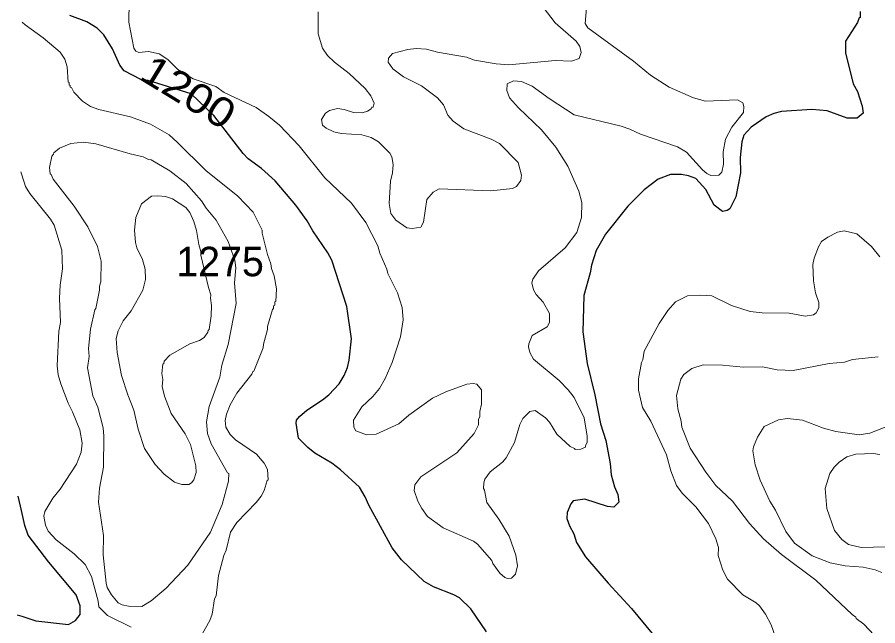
# Model space of a CAD drawing. Extents: x 598.3 to 623.2, y 6902.2 to 6930.1.
# Drawn here: x 598.43 to 600.767, y 6915.078 to 6916.731 of the extents above; entities that cross this region are included whole.
import ezdxf
from ezdxf.enums import TextEntityAlignment as Align

# ---------------------------------------------------------------- set-up
doc = ezdxf.new("R2010")
doc.units = 0
doc.header["$LTSCALE"] = 0.032
doc.layers.add('1', color=7, linetype='Continuous', lineweight=25)
doc.layers.add('2', color=7, linetype='Continuous', lineweight=13)
doc.layers.add('21', color=7, linetype='Continuous')
doc.layers.add('61', color=7, linetype='Continuous')

msp = doc.modelspace()

# ---------------------------------------------------------------- linework, layer by layer
at = {"layer": '1'}
for points in [[(600.719, 6916.7473), (600.719, 6916.7309), (600.7158, 6916.7296), (600.7118, 6916.717), (600.6795, 6916.6668), (600.6793, 6916.6345), (600.6999, 6916.5509), (600.712, 6916.5299), (600.7239, 6916.4898), (600.7269, 6916.4708), (600.7106, 6916.457), (600.6834, 6916.457), (600.6297, 6916.4772), (600.5876, 6916.4812), (600.5053, 6916.4755), (600.4842, 6916.4698), (600.4632, 6916.4609), (600.4225, 6916.4332), (600.4031, 6916.4108), (600.3976, 6916.3926), (600.3927, 6916.3508), (600.3936, 6916.3088), (600.3812, 6916.2431), (600.3648, 6916.2107)], [(599.3178, 6915.7583), (599.3268, 6915.7796), (599.3316, 6915.8002), (599.3379, 6915.8577), (599.3253, 6915.9454), (599.2845, 6916.0711), (599.2734, 6916.0916), (599.2328, 6916.1509), (599.217, 6916.1783), (599.1868, 6916.2211), (599.1306, 6916.2871), (599.093, 6916.3207), (599.0569, 6916.3466), (599.0432, 6916.3611), (598.9638, 6916.4646), (598.9024, 6916.5237), (598.7856, 6916.5597), (598.7659, 6916.5624), (598.7206, 6916.5857), (598.7081, 6916.6013), (598.6887, 6916.6458), (598.6647, 6916.6833), (598.6467, 6916.7013), (598.6191, 6916.7187), (598.5726, 6916.7357)], [(600.3648, 6916.2107), (600.358, 6916.206), (600.3451, 6916.2037), (600.3228, 6916.221), (600.2995, 6916.2637), (600.2729, 6916.2934), (600.2524, 6916.3007), (600.2336, 6916.3039), (600.2039, 6916.3046), (600.17, 6916.2916), (600.1319, 6916.2624), (600.0879, 6916.2184), (600.027, 6916.142), (600.0017, 6916.0974), (599.9889, 6916.0581), (599.9857, 6916.0371), (599.9687, 6915.9755), (599.966, 6915.8771), (599.9775, 6915.7907), (599.9987, 6915.7058), (600.0141, 6915.6264), (600.0285, 6915.5818), (600.0398, 6915.519), (600.0427, 6915.4885), (600.0519, 6915.4559), (600.0609, 6915.4345), (600.0632, 6915.4139), (600.0496, 6915.4006), (600.0329, 6915.4021), (599.971, 6915.4223), (599.9394, 6915.4173), (599.9329, 6915.4095), (599.923, 6915.386), (599.9225, 6915.3697), (599.9292, 6915.3501), (599.941, 6915.328), (599.9488, 6915.3041), (599.9733, 6915.2658), (600.0344, 6915.194), (600.0979, 6915.1255), (600.1538, 6915.0569)], [(599.7041, 6915.0619), (599.6612, 6915.124), (599.6308, 6915.1538), (599.6159, 6915.1624), (599.5601, 6915.1837), (599.5351, 6915.1981), (599.4732, 6915.2572), (599.4484, 6915.2898), (599.3846, 6915.4061), (599.3751, 6915.4283), (599.3592, 6915.4545), (599.3075, 6915.5023), (599.2839, 6915.52), (599.2383, 6915.5473), (599.2188, 6915.5627), (599.194, 6915.5878), (599.1875, 6915.6285), (599.1881, 6915.637), (599.196, 6915.6469), (599.2166, 6915.6644), (599.2591, 6915.6918), (599.2759, 6915.706), (599.3038, 6915.7354), (599.3178, 6915.7583)], [(598.4298, 6915.1084), (598.4423, 6915.1042), (598.4803, 6915.0916), (598.5687, 6915.0817), (598.5881, 6915.0927), (598.6011, 6915.1089), (598.6012, 6915.1326), (598.5901, 6915.1623), (598.5156, 6915.2515), (598.4596, 6915.3243), (598.4506, 6915.351), (598.4412, 6915.3917), (598.4324, 6915.4299)]]:
    msp.add_lwpolyline(points, dxfattribs=at)
at = {"layer": '2'}
for points in [[(598.7342, 6916.7732), (598.7326, 6916.7182), (598.7467, 6916.6478), (598.7518, 6916.6394), (598.7603, 6916.6357), (598.7862, 6916.6382), (598.8154, 6916.6316), (598.8388, 6916.6162), (598.8659, 6916.5894), (598.9076, 6916.5642), (598.9692, 6916.5434), (598.9919, 6916.5272), (599.0788, 6916.4862), (599.1127, 6916.4622), (599.1418, 6916.4379), (599.1959, 6916.3821), (599.2655, 6916.2955), (599.3376, 6916.2267), (599.3765, 6916.1734), (599.4089, 6916.1102), (599.4141, 6916.0902), (599.4334, 6916.0468), (599.4361, 6916.0349), (599.4625, 6915.9823), (599.4756, 6915.9429), (599.478, 6915.909), (599.4707, 6915.8635), (599.4479, 6915.7933), (599.4291, 6915.7496), (599.4137, 6915.723), (599.3953, 6915.7014), (599.3657, 6915.6727), (599.3429, 6915.6366), (599.3437, 6915.6178), (599.3494, 6915.6079), (599.3786, 6915.5973), (599.4045, 6915.5989), (599.4657, 6915.627), (599.4937, 6915.6508), (599.5571, 6915.6963), (599.5938, 6915.7138), (599.6508, 6915.7349), (599.6677, 6915.7365), (599.6781, 6915.7346), (599.6902, 6915.7188), (599.6909, 6915.6806), (599.6863, 6915.6606), (599.6861, 6915.6456), (599.6829, 6915.6391), (599.6828, 6915.6243), (599.671, 6915.601), (599.6238, 6915.5479), (599.5259, 6915.4831), (599.5096, 6915.461), (599.5081, 6915.4456), (599.5179, 6915.4165), (599.5288, 6915.3964), (599.5442, 6915.375), (599.5864, 6915.3443), (599.6691, 6915.3082), (599.6794, 6915.3003), (599.7185, 6915.2556), (599.721, 6915.247), (599.7408, 6915.2212), (599.7536, 6915.2094)], [(599.7903, 6916.3366), (599.7994, 6916.3026), (599.7976, 6916.2878), (599.7858, 6916.2718), (599.7748, 6916.2658), (599.7159, 6916.2601), (599.5759, 6916.2657), (599.5594, 6916.2565), (599.5421, 6916.2367), (599.5327, 6916.1745), (599.5256, 6916.1613), (599.5025, 6916.1575), (599.4881, 6916.1591), (599.4583, 6916.1804), (599.4447, 6916.1984), (599.4401, 6916.2257), (599.4433, 6916.2864), (599.4489, 6916.3086), (599.4505, 6916.3317), (599.4467, 6916.352), (599.4416, 6916.3621), (599.4106, 6916.3931), (599.3909, 6916.405), (599.3658, 6916.4123), (599.3092, 6916.4156), (599.29, 6916.4198), (599.2687, 6916.43), (599.2586, 6916.4378), (599.2564, 6916.4536), (599.2667, 6916.4707), (599.2776, 6916.4777), (599.2995, 6916.4836), (599.3175, 6916.4811), (599.3428, 6916.4728), (599.3661, 6916.4715), (599.3808, 6916.4758), (599.3909, 6916.4825), (599.3931, 6916.4867), (599.3965, 6916.4874), (599.3988, 6916.4984), (599.3897, 6916.5179), (599.3748, 6916.5375), (599.3311, 6916.5788), (599.291, 6916.609), (599.2728, 6916.6274), (599.2584, 6916.6477), (599.2474, 6916.686), (599.2474, 6916.7465)], [(599.8578, 6916.7584), (599.8905, 6916.7163), (599.9479, 6916.6662), (599.9572, 6916.6521), (599.9614, 6916.6357), (599.9562, 6916.6196), (599.9354, 6916.6124), (599.8906, 6916.6139), (599.7648, 6916.6019), (599.7304, 6916.6052), (599.6714, 6916.6152), (599.6502, 6916.6229), (599.5709, 6916.6367), (599.5415, 6916.6448), (599.5135, 6916.6463), (599.4905, 6916.6439), (599.4492, 6916.6328), (599.4377, 6916.6204), (599.4369, 6916.6093), (599.45, 6916.5911), (599.4792, 6916.5693), (599.5277, 6916.545), (599.5708, 6916.5123), (599.587, 6916.4936), (599.5996, 6916.4658), (599.6134, 6916.4495), (599.643, 6916.4282), (599.7172, 6916.4001), (599.7393, 6916.3882), (599.7903, 6916.3366)], [(599.7536, 6915.2094), (599.7612, 6915.2063), (599.772, 6915.208), (599.7825, 6915.2189), (599.7882, 6915.2412), (599.784, 6915.2697), (599.7653, 6915.3215), (599.7375, 6915.3676), (599.7049, 6915.4133), (599.699, 6915.447), (599.6959, 6915.4508), (599.6966, 6915.4667), (599.7, 6915.4769), (599.7137, 6915.4968), (599.7474, 6915.5226), (599.7572, 6915.5343), (599.7798, 6915.5765), (599.7943, 6915.625), (599.8027, 6915.6417), (599.8217, 6915.6605), (599.8365, 6915.6635), (599.8645, 6915.643), (599.8757, 6915.6318), (599.8951, 6915.599), (599.9315, 6915.5655), (599.9436, 6915.5598), (599.9454, 6915.5568), (599.9603, 6915.558), (599.9726, 6915.5635), (599.9728, 6915.5681), (599.9775, 6915.5757), (599.9776, 6915.5933), (599.9695, 6915.6432), (599.942, 6915.6982), (599.9259, 6915.7192), (599.9012, 6915.7447), (599.8317, 6915.8023), (599.8216, 6915.8205), (599.818, 6915.8357), (599.8187, 6915.8445), (599.8285, 6915.8665), (599.8693, 6915.8907), (599.8756, 6915.902), (599.8755, 6915.9264), (599.8577, 6915.9574), (599.8392, 6915.9783), (599.8315, 6915.9908), (599.827, 6916.0102), (599.8299, 6916.0201), (599.8453, 6916.0428), (599.9174, 6916.1046), (599.9496, 6916.1464), (599.9621, 6916.1871), (599.9629, 6916.2278), (599.9547, 6916.2589), (599.9254, 6916.3272), (599.8927, 6916.3782), (599.8535, 6916.4256), (599.7907, 6916.485), (599.7669, 6916.5129), (599.759, 6916.532), (599.7605, 6916.5505), (599.7771, 6916.5589), (599.7992, 6916.5565), (599.8284, 6916.5444), (599.8748, 6916.5105), (599.9425, 6916.4664), (600.0696, 6916.4359), (600.0936, 6916.4276), (600.1227, 6916.4135), (600.2226, 6916.379), (600.2472, 6916.3652), (600.2908, 6916.3168), (600.3027, 6916.3065), (600.3133, 6916.3014), (600.3347, 6916.3023), (600.3434, 6916.3106), (600.3474, 6916.3319), (600.3467, 6916.3657), (600.3535, 6916.4004), (600.3708, 6916.4324), (600.4018, 6916.4728), (600.4033, 6916.4885), (600.4002, 6916.4986), (600.3856, 6916.5069), (600.2987, 6916.5032), (600.2663, 6916.5125), (600.2, 6916.5415), (600.1497, 6916.5744), (600.1036, 6916.6117), (599.9792, 6916.7022), (599.9719, 6916.7146), (599.9759, 6916.7566)], [(598.4429, 6916.7177), (598.4517, 6916.7112), (598.5, 6916.6756), (598.5461, 6916.6367), (598.5593, 6916.6178), (598.5653, 6916.597), (598.5683, 6916.5552), (598.5706, 6916.5538), (598.5707, 6916.5478), (598.5736, 6916.546), (598.5739, 6916.5414), (598.577, 6916.5403), (598.5832, 6916.5278), (598.6068, 6916.5035), (598.6292, 6916.4891), (598.651, 6916.4805), (598.7375, 6916.4605), (598.7914, 6916.4412), (598.8426, 6916.4115), (598.8646, 6916.3922), (598.9419, 6916.3148), (599.0286, 6916.245), (599.0708, 6916.2019), (599.0951, 6916.1533), (599.0953, 6916.1447), (599.1098, 6916.0868), (599.1185, 6916.0617), (599.1199, 6916.0485), (599.1276, 6916.0285), (599.1341, 6915.9936), (599.1324, 6915.9593), (599.1292, 6915.958), (599.1291, 6915.9496), (599.126, 6915.9475), (599.1259, 6915.9399), (599.1228, 6915.9378), (599.1099, 6915.8916), (599.1097, 6915.883), (599.0986, 6915.843), (599.0981, 6915.8336), (599.0724, 6915.7698), (599.0693, 6915.7686), (599.0668, 6915.7616), (599.0262, 6915.7101), (599.0082, 6915.6783), (598.9981, 6915.6534), (598.9941, 6915.6356), (598.9964, 6915.6178), (599.0079, 6915.5978), (599.0226, 6915.5833), (599.0794, 6915.5442), (599.1008, 6915.5203), (599.1095, 6915.5031), (599.1113, 6915.4745), (599.1088, 6915.473), (599.1006, 6915.4453), (599.0922, 6915.4301), (599.0785, 6915.413), (599.0261, 6915.3591), (599.0087, 6915.3328), (598.9972, 6915.2839), (598.9911, 6915.2692), (598.9766, 6915.2146), (598.9698, 6915.1596), (598.9657, 6915.1514), (598.9588, 6915.1099), (598.9526, 6915.0927), (598.9332, 6915.0574)], [(598.5467, 6916.004), (598.5528, 6916.0476), (598.5512, 6916.0983), (598.53, 6916.1666), (598.5204, 6916.1825), (598.4645, 6916.2529), (598.4526, 6916.2713), (598.4485, 6916.2838), (598.4395, 6916.3111)], [(600.4206, 6915.9316), (600.4526, 6915.9284), (600.5263, 6915.9275), (600.5696, 6915.9195), (600.5921, 6915.9228), (600.5992, 6915.9283), (600.6066, 6915.9419), (600.6064, 6915.9564), (600.5976, 6915.9831), (600.592, 6916.0152), (600.5904, 6916.0597), (600.5939, 6916.077), (600.6054, 6916.1075), (600.614, 6916.122), (600.6313, 6916.1344), (600.657, 6916.1475), (600.6759, 6916.1508), (600.7096, 6916.1427), (600.7495, 6916.109), (600.7726, 6916.0808)], [(598.7393, 6915.0744), (598.6752, 6915.1064), (598.6515, 6915.1296), (598.6499, 6915.1447), (598.6315, 6915.2122), (598.6143, 6915.2451), (598.5846, 6915.2741), (598.5359, 6915.3121), (598.5142, 6915.3355), (598.5068, 6915.3514), (598.5019, 6915.376), (598.505, 6915.389), (598.5268, 6915.4246), (598.5465, 6915.4494), (598.5907, 6915.517), (598.6039, 6915.5501), (598.6062, 6915.5742), (598.5998, 6915.6108), (598.5802, 6915.6598), (598.5678, 6915.683), (598.5479, 6915.7357), (598.5414, 6915.7602), (598.5383, 6915.784), (598.5432, 6915.879), (598.5471, 6915.9019), (598.5447, 6915.9682), (598.5467, 6916.004)], [(600.4891, 6915.0476), (600.4774, 6915.0806), (600.4614, 6915.1094), (600.4455, 6915.1323), (600.4368, 6915.141), (600.4, 6915.1619), (600.3585, 6915.2051), (600.3456, 6915.2294), (600.3336, 6915.2688), (600.3344, 6915.291), (600.3273, 6915.3145), (600.3074, 6915.3558), (600.2725, 6915.401), (600.2351, 6915.4383), (600.2201, 6915.4593), (600.2043, 6915.4988), (600.193, 6915.5425), (600.1506, 6915.6339), (600.1281, 6915.6709), (600.1167, 6915.7182), (600.1168, 6915.7492), (600.1248, 6915.7936), (600.1289, 6915.8005), (600.1321, 6915.8245), (600.1731, 6915.8995), (600.1968, 6915.9346), (600.2172, 6915.9582), (600.2497, 6915.9745), (600.2851, 6915.976), (600.3164, 6915.9744), (600.3698, 6915.9483), (600.4206, 6915.9316)], [(600.7682, 6915.8085), (600.6981, 6915.8012), (600.676, 6915.7945), (600.6348, 6915.7906), (600.5367, 6915.7721), (600.4935, 6915.7738), (600.4538, 6915.7817), (600.4024, 6915.781), (600.3453, 6915.7866), (600.2924, 6915.7874), (600.2622, 6915.7776), (600.2397, 6915.7605), (600.2317, 6915.7483), (600.2204, 6915.7036), (600.2237, 6915.6674), (600.2332, 6915.6342), (600.2349, 6915.6178), (600.257, 6915.5606), (600.3002, 6915.4952), (600.327, 6915.4597), (600.3723, 6915.4169), (600.418, 6915.3558), (600.4566, 6915.3141), (600.5052, 6915.272), (600.5982, 6915.2024), (600.6975, 6915.1086), (600.7075, 6915.1019), (600.7082, 6915.0982), (600.7293, 6915.0826), (600.8397, 6914.9648)], [(600.7779, 6915.2231), (600.7598, 6915.2305), (600.7269, 6915.2379), (600.6783, 6915.2411), (600.6373, 6915.2489), (600.5884, 6915.2683), (600.5409, 6915.3025), (600.5171, 6915.3348), (600.489, 6915.3926), (600.4739, 6915.4165), (600.4474, 6915.4742), (600.4341, 6915.5153), (600.4277, 6915.5539), (600.429, 6915.5647), (600.44, 6915.5905), (600.4582, 6915.6197), (600.4967, 6915.6378), (600.5213, 6915.6417), (600.5626, 6915.6368), (600.6197, 6915.6152), (600.6524, 6915.6062), (600.7165, 6915.5973), (600.7452, 6915.6013), (600.787, 6915.6174)], [(600.7722, 6915.5439), (600.7542, 6915.5463), (600.7073, 6915.5446), (600.6829, 6915.5374), (600.6615, 6915.5227), (600.6479, 6915.5092), (600.6368, 6915.4919), (600.6235, 6915.451), (600.6281, 6915.3967), (600.6495, 6915.3372), (600.6687, 6915.3125), (600.6873, 6915.299), (600.7217, 6915.2913), (600.7886, 6915.2928)]]:
    msp.add_lwpolyline(points, dxfattribs=at)
for points in [[(598.5237, 6916.3543), (598.5285, 6916.3592), (598.529, 6916.3635), (598.5445, 6916.3758), (598.5758, 6916.3881), (598.6098, 6916.3921), (598.6435, 6916.3872), (598.7368, 6916.3599), (598.7717, 6916.3524), (598.7865, 6916.3452), (598.794, 6916.3443), (598.8442, 6916.3144), (598.8884, 6916.28), (598.9302, 6916.2325), (598.9431, 6916.213), (598.9702, 6916.1798), (599.0029, 6916.1224), (599.0208, 6916.0719), (599.0231, 6916.0502), (599.02, 6916.01), (599.0247, 6915.9537), (599.0028, 6915.842), (598.9852, 6915.7858), (598.9803, 6915.7537), (598.9508, 6915.6743), (598.9438, 6915.6327), (598.9467, 6915.6003), (598.9567, 6915.5725), (599.0013, 6915.4938), (599.0045, 6915.4917), (599.0037, 6915.4715), (598.9865, 6915.408), (598.9544, 6915.3328), (598.8934, 6915.2433), (598.8344, 6915.1802), (598.7932, 6915.1456), (598.7678, 6915.1302), (598.7324, 6915.1314), (598.7147, 6915.1355), (598.7035, 6915.1409), (598.6857, 6915.1623), (598.6743, 6915.1819), (598.671, 6915.1936), (598.663, 6915.2708), (598.6637, 6915.3231), (598.6507, 6915.4141), (598.6531, 6915.452), (598.6645, 6915.5088), (598.6653, 6915.5935), (598.6628, 6915.6164), (598.6484, 6915.6723), (598.6351, 6915.7026), (598.6209, 6915.7791), (598.6248, 6915.8101), (598.6233, 6915.8313), (598.6289, 6915.8843), (598.6403, 6915.9369), (598.6435, 6915.9402), (598.6531, 6915.9899), (598.6532, 6916.0011), (598.6572, 6916.0126), (598.658, 6916.0691), (598.6479, 6916.1087), (598.6215, 6916.1617), (598.5843, 6916.2181), (598.5277, 6916.2918), (598.522, 6916.3045), (598.5189, 6916.3059), (598.5173, 6916.3236)], [(598.7943, 6916.2449), (598.8113, 6916.2465), (598.8327, 6916.2441), (598.8514, 6916.2379), (598.8877, 6916.2142), (598.8989, 6916.2008), (598.9097, 6916.1763), (598.917, 6916.1517), (598.9228, 6916.1143), (598.9284, 6916.095), (598.9286, 6916.0848), (598.9492, 6915.9972), (598.9559, 6915.977), (598.9543, 6915.9686), (598.9575, 6915.948), (598.9569, 6915.9201), (598.951, 6915.8833), (598.9479, 6915.8803), (598.9476, 6915.8757), (598.9371, 6915.8618), (598.9245, 6915.8532), (598.8988, 6915.8439), (598.8447, 6915.8136), (598.8289, 6915.7975), (598.828, 6915.7909), (598.8249, 6915.7887), (598.8224, 6915.7635), (598.8248, 6915.7476), (598.8231, 6915.7279), (598.8301, 6915.7018), (598.8476, 6915.6545), (598.8863, 6915.5996), (598.9007, 6915.5711), (598.9145, 6915.5128), (598.9154, 6915.4947), (598.9098, 6915.4749), (598.9033, 6915.4664), (598.8958, 6915.462), (598.8768, 6915.4616), (598.8566, 6915.4687), (598.8288, 6915.4903), (598.8041, 6915.5168), (598.7751, 6915.5597), (598.758, 6915.6128), (598.7464, 6915.6639), (598.7301, 6915.7055), (598.7132, 6915.7581), (598.7016, 6915.8208), (598.6986, 6915.8587), (598.7037, 6915.8791), (598.7176, 6915.9067), (598.7392, 6915.9334), (598.7712, 6915.99), (598.7778, 6916.019), (598.7777, 6916.0471), (598.7701, 6916.0731), (598.7548, 6916.1046), (598.7512, 6916.1191), (598.748, 6916.1526), (598.752, 6916.1876), (598.7671, 6916.2244)]]:
    msp.add_lwpolyline(points, close=True, dxfattribs=at)

# ---------------------------------------------------------------- texts
at = {"layer": '21'}
msp.add_text('1275', height=0.08, dxfattribs=at).set_placement((598.8616, 6916.0278))
at = {"layer": '61', "width": 1.15}
msp.add_text('1200', height=0.08, rotation=328.643, dxfattribs=at).set_placement((598.874, 6916.4941), align=Align.CENTER)

doc.saveas('drawing.dxf')
